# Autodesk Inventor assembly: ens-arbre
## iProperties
Author: robert
Shininess: 41.0
Angle Display Precision: 2
Document Length Units: 11269
Document Angle Units: 11283
Document Time Units: 11279
Document Mass Units: 11290
Document Length Units Precision: 3
Document Angle Units Precision: 2
Compacted: True
PropertySet Name: _Private Model Information
Created: 2002-09
Part Number: ens-arbre
Document SubType Name: Assemblage
Designer: robert
Control State: 0
Master: False
Checked Out: False
PropertySet Name: Design Tracking Control
Density: 0.0
Volumn: 0.0
Area: 0.0
PropertySet Name: Model Information
